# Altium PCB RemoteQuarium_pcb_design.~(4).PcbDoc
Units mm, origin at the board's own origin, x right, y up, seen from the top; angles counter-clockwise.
Board outline 63.5 x 89.41 mm, 2 copper layers (F.Cu, B.Cu); 22 components, 37 nets, 118 pads, 0 vias.
Unrouted connection lines stored in the file: 5.
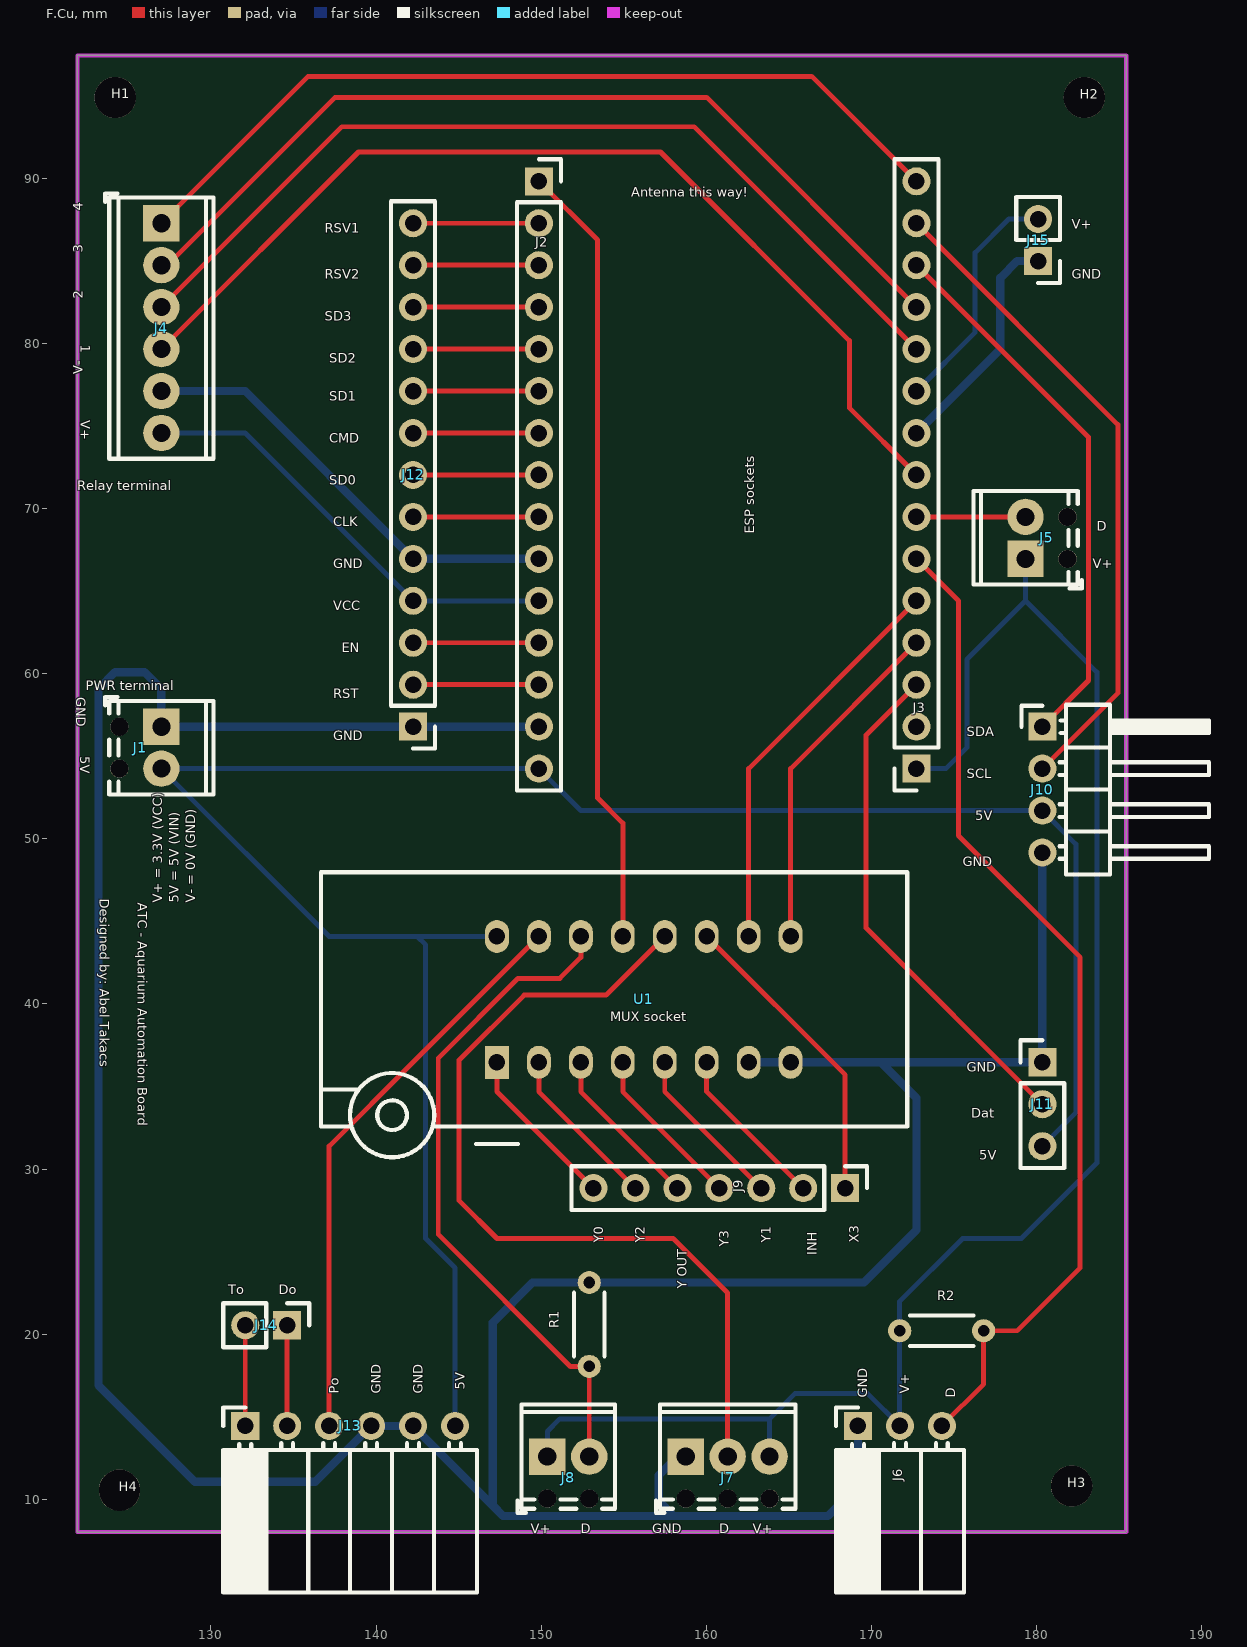
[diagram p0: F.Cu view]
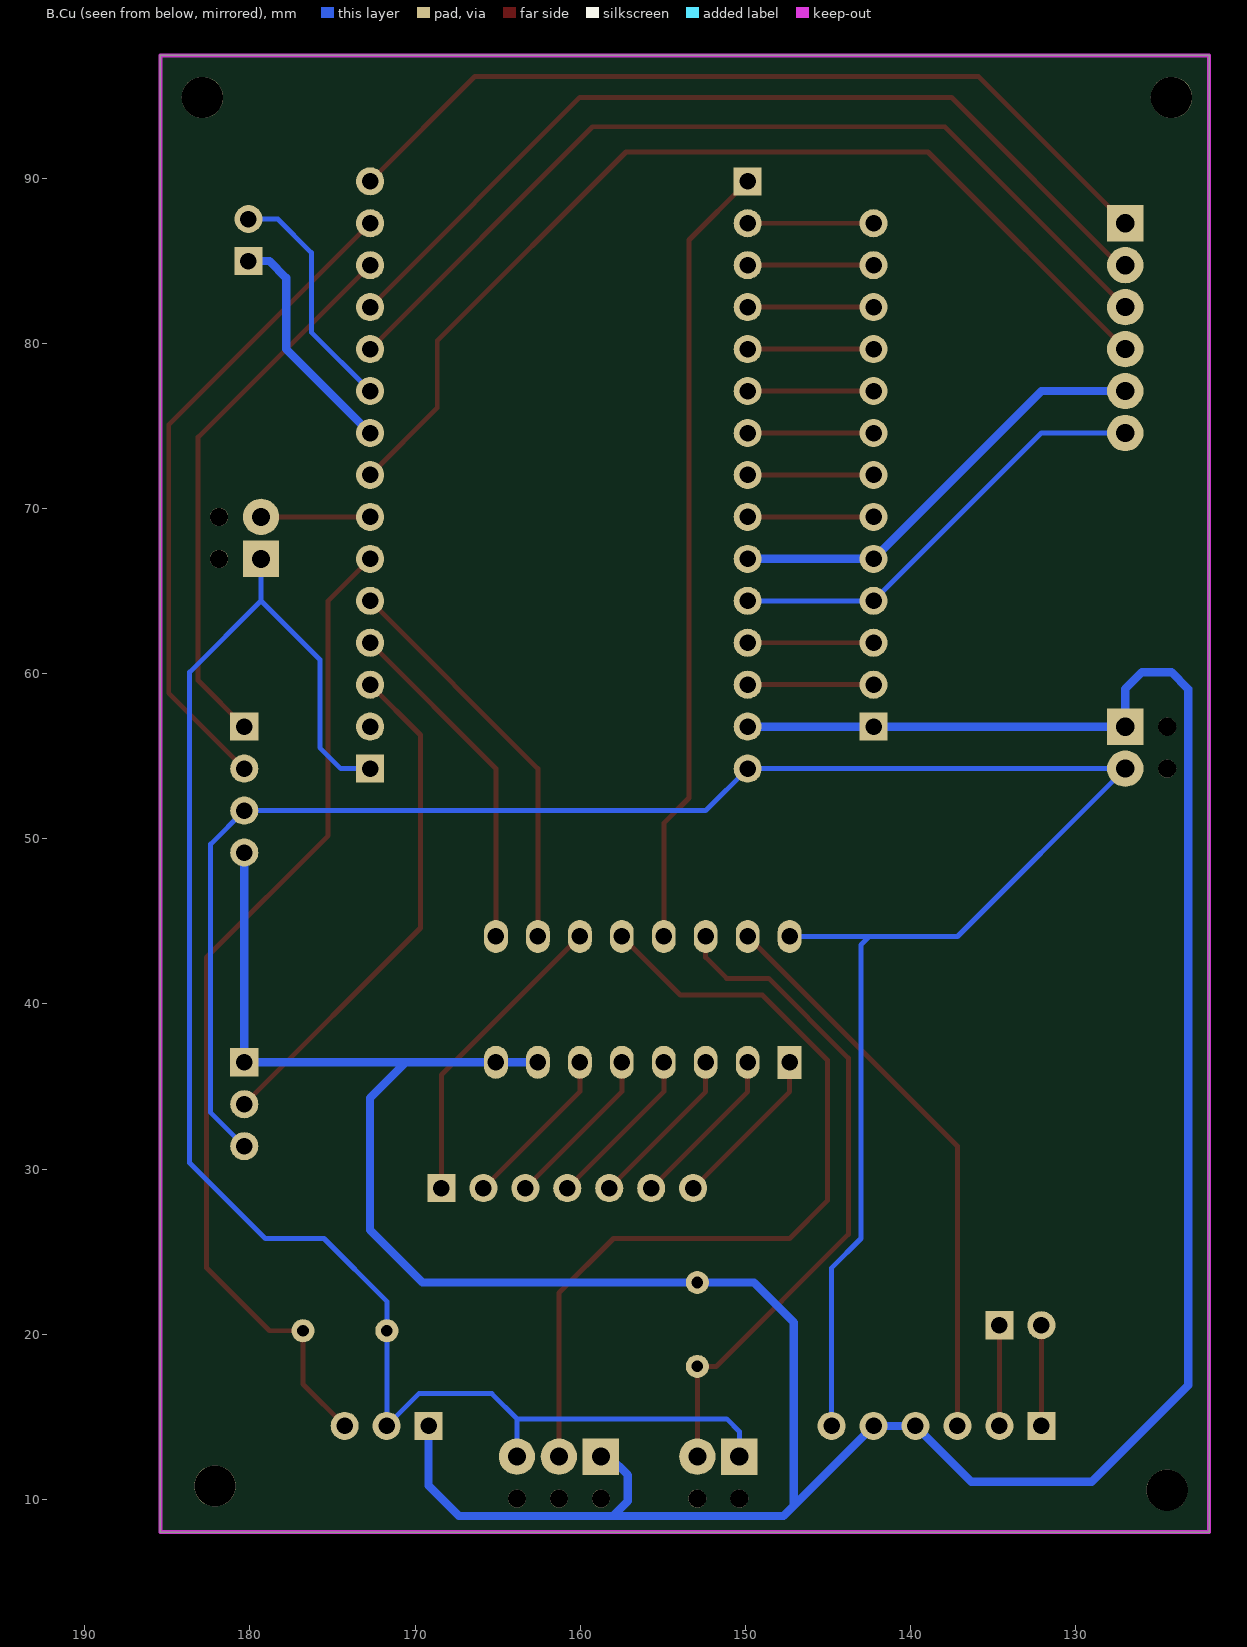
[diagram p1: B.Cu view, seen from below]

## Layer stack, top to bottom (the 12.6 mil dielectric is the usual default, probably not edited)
F.Mask: solder mask 0.0102, Solder Resist, Dk 3.5
F.Cu: signal copper 0.0356
Dielectric 1: dielectric 0.32, FR-4, Dk 4.8
B.Cu: signal copper 0.0356
B.Mask: solder mask 0.0102, Solder Resist, Dk 3.5

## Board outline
185.42,8.018 185.42,97.426 121.92,97.426 121.92,8.018 185.42,8.018

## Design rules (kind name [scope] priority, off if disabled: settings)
MinimumSolderMaskSliver [All] p1: minsoldermaskwidth=0
PolygonConnect [All] p1: connectstyle=Direct reliefconductorwidth=0.254 reliefentries=4 polygonreliefangle="90 Angle" airgapwidth=0.254
RoutingVias [All] p1: holewidth=0.711 width=1.27 viastyle="Through Hole" minholewidth=0.711 minwidth=1.27 maxholewidth=0.711 maxwidth=1.27
SilkToSilkClearance [All] p1: silktosilkclearance=0
SilkToSolderMaskClearance [IsPad] p1: minsilkscreentomaskgap=0 clearancetoexposedcopper=TRUE
SolderMaskExpansion [All] p1: expansion=0.102 istentingtop=FALSE
Width [All] p1: maxlimit=10 minlimit=0.254 preferedwidth=0.254 minimp=50.000000 maximp=50.000000 favimp=50.000000
26 further rules are at their usual default settings.

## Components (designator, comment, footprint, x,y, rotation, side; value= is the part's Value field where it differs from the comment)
H1 "MountingHole" MountingHole_2.5mm 124.206,94.886 r0 top
H2 "MountingHole" MountingHole_2.5mm 182.88,94.886 r0 top
H3 "MountingHole" MountingHole_2.5mm 182.118,10.812 r0 top
H4 "MountingHole" MountingHole_2.5mm 124.46,10.558 r0 top
J1 "Power_terminal" TerminalBlock_Phoenix_MPT-0,5-2-2.54_1x02_P2.54mm_Horizontal 127,56.786 r270 top
J2 "ESP left side sockets" PinSocket_1x15_P2.54mm_Vertical 149.86,89.806 r0 top
J3 "ESP right side sockets" PinSocket_1x15_P2.54mm_Vertical 172.72,54.246 r180 top
J4 "Relay_terminal" TerminalBlock_Phoenix_MPT-0,5-6-2.54_1x06_P2.54mm_Horizontal 127,87.266 r270 top
J5 "Calibration_btn" TerminalBlock_Phoenix_MPT-0,5-2-2.54_1x02_P2.54mm_Horizontal 179.324,66.946 r90 top
J6 "Temp_sensor_socket" PinSocket_1x03_P2.54mm_Horizontal 169.179,14.45 r90 top
J7 "Water_sensor_terminal" TerminalBlock_Phoenix_MPT-0,5-3-2.54_1x03_P2.54mm_Horizontal 158.75,12.59 r0 top
J8 "Light_sensor_terminal" TerminalBlock_Phoenix_MPT-0,5-2-2.54_1x02_P2.54mm_Horizontal 150.368,12.59 r0 top
J9 "MUX_pins" PinHeader_1x07_P2.54mm_Vertical 168.402,28.846 r270 top
J10 "LCD_pins" PinHeader_1x04_P2.54mm_Horizontal 180.34,56.786 r0 top
J11 "Feeder_servo_pins" PinHeader_1x03_P2.54mm_Vertical 180.34,36.466 r0 top
J12 "ESP_pins" PinHeader_1x13_P2.54mm_Vertical 142.24,56.786 r180 top
J13 "PH_sensor_sockets" PinSocket_1x06_P2.54mm_Horizontal 132.08,14.45 r90 top
J14 "Ph_sesnor-pins" PinHeader_1x02_P2.54mm_Vertical 134.62,20.546 r270 top
J15 "Vcc-GND" PinHeader_1x02_P2.54mm_Vertical 180.086,84.98 r180 top
R1 "10000" R_Axial_DIN0204_L3.6mm_D1.6mm_P5.08mm_Horizontal 152.908,18.051 r90 top
R2 "4700R" R_Axial_DIN0204_L3.6mm_D1.6mm_P5.08mm_Horizontal 171.704,20.21 r0 top
U1 "CD4052BE" DIP_Socket-16_W4.3_W5.08_W7.62_W10.16_W10.9_3M_216-3340-00-0602J 147.32,36.466 r90 top

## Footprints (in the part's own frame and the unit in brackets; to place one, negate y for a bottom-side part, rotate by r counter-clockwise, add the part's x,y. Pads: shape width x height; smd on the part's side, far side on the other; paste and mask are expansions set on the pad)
DIP_Socket-16_W4.3_W5.08_W7.62_W10.16_W10.9_3M_216-3340-00-0602J [mm]
  rect 2x1.44 hole 1 paste-2 mask+0: 1(0,0)
  rrect100% 2x1.44 hole 1 paste-2 mask+0: 2(0,-2.54) 3(0,-5.08) 4(0,-7.62) 5(0,-10.16) 6(0,-12.7) 7(0,-15.24) 8(0,-17.78) 9(7.62,-17.78) 10(7.62,-15.24) 11(7.62,-12.7) 12(7.62,-10.16) 13(7.62,-7.62) 14(7.62,-5.08) 15(7.62,-2.54) 16(7.62,0)
  silkscreen extent -5.75,-24.84 11.51,10.66
MountingHole_2.5mm [mm]
  round 2.5 hole 2.5 paste-2.5 mask+0: Un1(0,0)
PinHeader_1x02_P2.54mm_Vertical [mm]
  rect 1.7x1.7 hole 1 paste-1.7 mask+0: 1(0,0)
  rrect100% 1.7x1.7 hole 1 paste-1.7 mask+0: 2(0,-2.54)
  silkscreen extent -1.33,-3.87 1.33,1.33
PinHeader_1x03_P2.54mm_Vertical [mm]
  rect 1.7x1.7 hole 1 paste-1.7 mask+0: 1(0,0)
  rrect100% 1.7x1.7 hole 1 paste-1.7 mask+0: 2(0,-2.54) 3(0,-5.08)
  silkscreen extent -1.33,-6.41 1.33,1.33
PinHeader_1x04_P2.54mm_Horizontal [mm]
  rect 1.7x1.7 hole 1 paste-1.7 mask+0: 1(0,0)
  rrect100% 1.7x1.7 hole 1 paste-1.7 mask+0: 2(0,-2.54) 3(0,-5.08) 4(0,-7.62)
  silkscreen extent -1.27,-8.95 10.1,1.33
PinHeader_1x07_P2.54mm_Vertical [mm]
  rect 1.7x1.7 hole 1 paste-1.7 mask+0: 1(0,0)
  rrect100% 1.7x1.7 hole 1 paste-1.7 mask+0: 2(0,-2.54) 3(0,-5.08) 4(0,-7.62) 5(0,-10.16) 6(0,-12.7) 7(0,-15.24)
  silkscreen extent -1.33,-16.57 1.33,1.33
PinHeader_1x13_P2.54mm_Vertical [mm]
  rect 1.7x1.7 hole 1 paste-1.7 mask+0: 1(0,0)
  rrect100% 1.7x1.7 hole 1 paste-1.7 mask+0: 2(0,-2.54) 3(0,-5.08) 4(0,-7.62) 5(0,-10.16) 6(0,-12.7) 7(0,-15.24) 8(0,-17.78) 9(0,-20.32) 10(0,-22.86) 11(0,-25.4) 12(0,-27.94) 13(0,-30.48)
  silkscreen extent -1.33,-31.81 1.33,1.33
PinSocket_1x03_P2.54mm_Horizontal [mm]
  rect 1.7x1.7 hole 1 paste-1.7 mask+0: 1(0,0)
  rrect100% 1.7x1.7 hole 1 paste-1.7 mask+0: 2(0,-2.54) 3(0,-5.08)
  silkscreen extent -10.09,-6.41 1.11,1.33
PinSocket_1x06_P2.54mm_Horizontal [mm]
  rect 1.7x1.7 hole 1 paste-1.7 mask+0: 1(0,0)
  rrect100% 1.7x1.7 hole 1 paste-1.7 mask+0: 2(0,-2.54) 3(0,-5.08) 4(0,-7.62) 5(0,-10.16) 6(0,-12.7)
  silkscreen extent -10.09,-14.03 1.11,1.33
PinSocket_1x15_P2.54mm_Vertical [mm]
  rect 1.7x1.7 hole 1 paste-1.7 mask+0: 1(0,0)
  rrect100% 1.7x1.7 hole 1 paste-1.7 mask+0: 2(0,-2.54) 3(0,-5.08) 4(0,-7.62) 5(0,-10.16) 6(0,-12.7) 7(0,-15.24) 8(0,-17.78) 9(0,-20.32) 10(0,-22.86) 11(0,-25.4) 12(0,-27.94) 13(0,-30.48) 14(0,-33.02) 15(0,-35.56)
  silkscreen extent -1.33,-36.89 1.33,1.33
R_Axial_DIN0204_L3.6mm_D1.6mm_P5.08mm_Horizontal [mm]
  round 1.4 hole 0.7 paste-1.4 mask+0: 1(0,0)
  rrect100% 1.4x1.4 hole 0.7 paste-1.4 mask+0: 2(5.08,0)
  silkscreen extent 0.62,-0.92 4.46,0.92
TerminalBlock_Phoenix_MPT-0,5-2-2.54_1x02_P2.54mm_Horizontal [mm]
  rect 2.2x2.2 hole 1.1 paste-2.2 mask+0: 1(0,0)
  round 2.2 hole 1.1 paste-2.2 mask+0: 2(2.54,0)
  round 1.1 hole 1.1 paste-1.1 mask+0: Un1(0,-2.54) Un2(2.54,-2.54)
  silkscreen extent -1.8,-3.4 4.1,3.16
TerminalBlock_Phoenix_MPT-0,5-3-2.54_1x03_P2.54mm_Horizontal [mm]
  rect 2.2x2.2 hole 1.1 paste-2.2 mask+0: 1(0,0)
  round 2.2 hole 1.1 paste-2.2 mask+0: 2(2.54,0) 3(5.08,0)
  round 1.1 hole 1.1 paste-1.1 mask+0: Un1(0,-2.54) Un2(2.54,-2.54) Un3(5.08,-2.54)
  silkscreen extent -1.8,-3.4 6.64,3.16
TerminalBlock_Phoenix_MPT-0,5-6-2.54_1x06_P2.54mm_Horizontal [mm]
  rect 2.2x2.2 hole 1.1 paste-2.2 mask+0: 1(0,0)
  round 2.2 hole 1.1 paste-2.2 mask+0: 2(2.54,0) 3(5.08,0) 4(7.62,0) 5(10.16,0) 6(12.7,0)
  silkscreen extent -1.8,-3.4 14.26,3.16

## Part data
H1 H2 H3 H4: library part MountingHole_2.5mm, "Mounting Hole 2.5mm, no annular"
J1 J5 J8: library part TerminalBlock_Phoenix_MPT-0,5-2-2.54_1x02_P2.54mm_Horizontal, "Terminal Block Phoenix MPT-0,5-2-2.54, 2 pins, pitch 2.54mm, size 5.54x6.2mm^2, drill diamater 1.1mm, pad diameter 2.2mm, see http://www.mouser.com/ds/2/324/ItemDetail_1725656-920552.pdf, script-generated using https://github.com/pointhi/kicad-footprint-generator/scripts/TerminalBlock_Phoenix"
J2 J3: library part PinSocket_1x15_P2.54mm_Vertical, "Through hole straight socket strip, 1x15, 2.54mm pitch, single row (from Kicad 4.0.7), script generated"
J4: library part TerminalBlock_Phoenix_MPT-0,5-6-2.54_1x06_P2.54mm_Horizontal, "Terminal Block Phoenix MPT-0,5-6-2.54, 6 pins, pitch 2.54mm, size 15.7x6.2mm^2, drill diamater 1.1mm, pad diameter 2.2mm, see http://www.mouser.com/ds/2/324/ItemDetail_1725672-916605.pdf, script-generated using https://github.com/pointhi/kicad-footprint-generator/scripts/TerminalBlock_Phoenix"
J6: library part PinSocket_1x03_P2.54mm_Horizontal, "Through hole angled socket strip, 1x03, 2.54mm pitch, 8.51mm socket length, single row (from Kicad 4.0.7), script generated"
J7: library part TerminalBlock_Phoenix_MPT-0,5-3-2.54_1x03_P2.54mm_Horizontal, "Terminal Block Phoenix MPT-0,5-3-2.54, 3 pins, pitch 2.54mm, size 8.08x6.2mm^2, drill diamater 1.1mm, pad diameter 2.2mm, see http://www.mouser.com/ds/2/324/ItemDetail_1725656-920552.pdf, script-generated using https://github.com/pointhi/kicad-footprint-generator/scripts/TerminalBlock_Phoenix"
J9: library part PinHeader_1x07_P2.54mm_Vertical, "Through hole straight pin header, 1x07, 2.54mm pitch, single row"
J10: library part PinHeader_1x04_P2.54mm_Horizontal, "Through hole angled pin header, 1x04, 2.54mm pitch, 6mm pin length, single row"
J11: library part PinHeader_1x03_P2.54mm_Vertical, "Through hole straight pin header, 1x03, 2.54mm pitch, single row"
J12: library part PinHeader_1x13_P2.54mm_Vertical, "Through hole straight pin header, 1x13, 2.54mm pitch, single row"
J13: library part PinSocket_1x06_P2.54mm_Horizontal, "Through hole angled socket strip, 1x06, 2.54mm pitch, 8.51mm socket length, single row (from Kicad 4.0.7), script generated"
J14 J15: library part PinHeader_1x02_P2.54mm_Vertical, "Through hole straight pin header, 1x02, 2.54mm pitch, single row"
R1 R2: library part R_Axial_DIN0204_L3.6mm_D1.6mm_P5.08mm_Horizontal, "Resistor, Axial_DIN0204 series, Axial, Horizontal, pin pitch=5.08mm, 0.167W, length*diameter=3.6*1.6mm^2, http://cdn-reichelt.de/documents/datenblatt/B400/1_4W%23YAG.pdf"
U1: library part DIP_Socket-16_W4.3_W5.08_W7.62_W10.16_W10.9_3M_216-3340-00-0602J, "3M 16-pin zero insertion force socket, through-hole, row spacing 7.62 mm (300 mils), http://multimedia.3m.com/mws/media/494546O/3mtm-dip-sockets-100-2-54-mm-ts0365.pdf", Package="PDIP-16 Texas Instruments"

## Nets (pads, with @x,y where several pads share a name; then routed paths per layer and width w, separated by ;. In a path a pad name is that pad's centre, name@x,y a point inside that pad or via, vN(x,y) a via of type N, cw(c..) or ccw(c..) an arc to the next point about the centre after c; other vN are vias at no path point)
A0: J2.1 U1.13 | length 47.8
  F.Cu w0.3: J2.1 153.416,86.25 153.416,52.468 154.94,50.944 154.94,48.912 U1.13
CLK: J2.9 J12.6 | length 7.6
  F.Cu w0.3: J12.6 J2.9
CMD: J2.7 J12.8 | length 7.6
  F.Cu w0.3: J12.8 J2.7
D0: J3.15 J4.1 | length 52
  F.Cu w0.3: J4.1 135.89,96.156 166.37,96.156 J3.15
D3: J3.12 J4.2 | length 55.2
  F.Cu w0.3: J4.2 127.36,84.726 137.52,94.886 160.02,94.886 J3.12
D4: J3.11 J4.3 | length 55.8
  F.Cu w0.3: J4.3 137.922,93.108 159.258,93.108 J3.11
D5: J3.8 J4.4 | length 61.1
  F.Cu w0.3: J4.4 138.938,91.584 157.226,91.584 168.656,80.154 168.656,76.09 J3.8
D6: J3.7 J5.2 | length 6.6
  F.Cu w0.3: J3.7 J5.2
D7: J3.6 J6.3 R2.2 | length 61.3
  F.Cu w0.3: J3.6 175.26,64.406 175.26,50.182 182.626,42.816 182.626,24.02 178.816,20.21 R2.2 176.784,16.975 J6.3
D8: J3.5 U1.10 | length 24.5
  F.Cu w0.3: U1.10 162.56,49.166 162.56,54.246 J3.5
Do: J13.2 J14.1 | length 6.1
  F.Cu w0.3: J13.2 J14.1
EN: J2.12 J12.3 | length 7.6
  F.Cu w0.3: J12.3 J2.12
GND: J1.1 J2.10 J2.14 J3.2 J3.9 J4.5 J6.1 J7.1 J10.4 J11.1 J12.1 J12.5 J13.4 J13.5 J15.1 R1.2 U1.7 U1.8 | length 256.1
  B.Cu w0.5: J4.5 132.08,77.106 J12.5 J2.10 ; J2.14 J12.1 J1.1 127,59.072 125.984,60.088 124.206,60.088 123.19,59.072 123.19,16.908 129.032,11.066 136.316,11.066 J13.4 J13.5 147.69,9 ; J7.1 158.242,12.59 157.119,11.467 157.119,9.903 158.022,9 ; U1.7 U1.8 170.561,36.466 170.624,36.403 ; J6.1 169.179,10.827 167.352,9 158.022,9 ; J3.9 177.8,79.646 177.8,83.964 178.816,84.98 J15.1 ; J10.4 J11.1 170.688,36.466 170.624,36.403 ; 147.69,9 158.022,9 ; 147.69,9 147.066,9.624 147.066,20.718 149.479,23.131 R1.2 169.545,23.131 172.72,26.306 172.72,34.307 170.624,36.403
INH: J9.2 U1.6 | length 10
  F.Cu w0.3: U1.6 160.02,34.688 J9.2
LIGHT_DAT: J8.2 R1.1 U1.14 | length 40.9
  F.Cu w0.3: U1.14 152.4,42.816 151.13,41.546 148.59,41.546 143.764,36.72 143.764,26.052 151.765,18.051 R1.1 J8.2@152.908,12.717
P0: J13.3 U1.15 | length 34.9
  F.Cu w0.3: J13.3 137.16,31.386 142.24,36.466 U1.15
RST: J2.13 J12.2 | length 7.6
  F.Cu w0.3: J12.2 J2.13
RSV1: J2.2 J12.13 | length 7.6
  F.Cu w0.3: J12.13 J2.2
RSV2: J2.3 J12.12 | length 7.6
  F.Cu w0.3: J12.12 J2.3
RX: J3.4 U1.9 | length 20.9
  F.Cu w0.3: U1.9 165.1,49.166 165.1,54.246 J3.4
SCL: J3.14 J10.2 | length 40
  F.Cu w0.3: J3.14 184.912,75.074 184.912,58.818 J10.2
SD0: J2.8 J12.7 | length 7.6
  F.Cu w0.3: J12.7 J2.8
SD1: J2.6 J12.9 | length 7.6
  F.Cu w0.3: J12.9 J2.6
SD2: J2.5 J12.10 | length 7.6
  F.Cu w0.3: J12.10 J2.5
SD3: J2.4 J12.11 | length 7.6
  F.Cu w0.3: J12.11 J2.4
SDA: J3.13 J10.1 | length 33.4
  F.Cu w0.3: J3.13 183.134,74.312 183.134,59.58 J10.1
T0: J13.1 J14.2 | length 6.1
  F.Cu w0.3: J13.1 J14.2
TX: J3.3 J11.2 | length 31.1
  F.Cu w0.3: J3.3 169.672,56.278 169.672,44.594 J11.2
VCC: J2.11 J3.1 J3.10 J4.6 J5.1 J6.2 J7.3 J8.1 J12.4 J15.2 R2.1 | length 144.3
  F.Cu w0.3: R2.1 R2.1@171.719,20.195
  B.Cu w0.3: J4.6 132.08,74.566 J12.4 J2.11 ; J8.1 150.368,14.114 151.13,14.876 163.83,14.876 ; J7.3 163.83,14.876 ; J6.2@171.719,13.875 J6.2 ; J3.1 174.498,54.246 175.768,55.516 175.768,60.85 179.324,64.406 ; J3.10 176.276,80.662 176.276,85.488 178.308,87.52 J15.2 ; J5.1 179.324,64.406 ; 163.83,14.876 165.354,16.4 169.769,16.4 J6.2 ; J6.2 171.704,14.465 R2.1 171.704,21.988 175.514,25.798 179.07,25.798 183.642,30.37 183.642,60.088 179.324,64.406
VIN: J1.2 J2.15 J10.3 J11.3 J13.6 U1.16 | length 132
  B.Cu w0.3: J13.6 144.78,24.02 143.002,25.798 143.002,43.578 142.494,44.086 142.24,44.086 ; U1.16 142.24,44.086 ; 160.02,51.706 160.274,51.706 ; J11.3 182.372,33.418 182.372,49.674 J10.3 160.274,51.706 ; 142.24,44.086 137.16,44.086 J1.2 J2.15 152.4,51.706 160.274,51.706
WATER_DAT: J7.2 U1.12 | length 52.5
  F.Cu w0.3: U1.12 153.924,40.53 148.964,40.53 145.034,36.6 145.034,28.084 147.32,25.798 157.988,25.798 161.29,22.496 J7.2
X3: J9.1 U1.11 | length 18.7
  F.Cu w0.3: U1.11 168.402,35.704 J9.1
Y: J9.5 U1.3 | length 10
  F.Cu w0.3: U1.3 152.4,34.688 J9.5
Y0: J9.7 U1.1 | length 10
  F.Cu w0.3: U1.1 147.32,34.688 J9.7
Y1: J9.3 U1.5 | length 10
  F.Cu w0.3: U1.5 157.48,34.688 J9.3
Y2: J9.6 U1.2 | length 10.3
  F.Cu w0.3: U1.2 149.86,34.688 J9.6 J9.6@155.956,28.846
Y3: J9.4 U1.4 | length 10
  F.Cu w0.3: U1.4 154.94,34.688 J9.4
pads on no net: H1.Un1 H2.Un1 H3.Un1 H4.Un1 J1.Un1 J1.Un2 J5.Un1 J5.Un2 J7.Un1 J7.Un2 J7.Un3 J8.Un1 J8.Un2

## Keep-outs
Edge.Cuts:
  lines w0: 121.92,8.018 185.42,8.018 185.42,97.426 121.92,97.426 121.92,8.018
  lines w0.254: 121.92,8.018 185.42,8.018 185.42,97.426 121.92,97.426 121.92,8.018

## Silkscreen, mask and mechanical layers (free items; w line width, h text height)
F.SilkS:
  text "Antenna this way!" at 155.448,88.662 h1
  text "4" at 122.454,88.028 h1 r90
  text "V+" at 182.118,86.731 h1
  text "RSV1" at 136.906,86.474 h1
  text "3" at 122.459,85.488 h1 r90
  text "RSV2" at 136.906,83.68 h1
  text "GND" at 182.118,83.68 h1
  text "2" at 122.454,82.694 h1 r90
  text "SD3" at 136.906,81.138 h1
  text "1" at 121.897,79.9 h1 r270
  text "SD2" at 137.16,78.6 h1
  text "V-" at 122.455,78.122 h1 r90
  text "SD1" at 137.16,76.314 h1
  text "V+" at 121.893,75.328 h1 r270
  text "CMD" at 137.16,73.774 h1
  text "SD0" at 137.16,71.232 h1
  text "Relay terminal" at 121.92,70.882 h1
  text "CLK" at 137.414,68.694 h1
  text "ESP sockets" at 163.1,68.47 h1 r90
  text "D" at 183.642,68.447 h1
  text "V+" at 183.388,66.157 h1
  text "GND" at 137.414,66.154 h1
  text "VCC" at 137.414,63.614 h1
  text "EN" at 137.922,61.081 h1
  text "PWR terminal" at 122.428,58.786 h1
  text "GND" at 121.636,58.564 h1 r270
  text "RST" at 137.414,58.28 h1
  text "SDA" at 175.768,55.994 h1
  text "GND" at 137.414,55.74 h1
  text "5V" at 121.892,55.008 h1 r270
  text "SCL" at 175.768,53.454 h1
  text "5V" at 176.276,50.916 h1
  text "GND" at 175.514,48.12 h1
  text "Designed by: Abel Takacs" at 123.062,46.372 h1 r270
  text "ATC - Aquarium Automation Board" at 125.35,46.118 h1 r270
  text "V+ = 3.3V (VCC) / 5V = 5V (VIN) / V- = 0V (GND)" at 129.272,46.118 h1 r90
  text "MUX socket" at 154.178,38.724 h1
  text "GND" at 175.768,35.674 h1
  text "Dat" at 176.022,32.882 h1
  text "5V" at 176.53,30.342 h1
  text "Y0" at 153.955,25.544 h1 r90
  text "Y2" at 156.49,25.544 h1 r90
  text "Y1" at 164.107,25.544 h1 r90
  text "X3" at 169.449,25.544 h1 r90
  text "Y3" at 161.575,25.29 h1 r90
  text "INH" at 166.901,24.782 h1 r90
  text "Y OUT" at 159.034,22.75 h1 r90
  text "To" at 131.064,22.214 h1
  text "Do" at 134.112,22.214 h1
  text "5V" at 145.57,16.654 h1 r90
  text "Po" at 137.95,16.4 h1 r90
  text "GND" at 140.492,16.4 h1 r90
  text "GND" at 143.032,16.4 h1 r90
  text "V+" at 172.493,16.4 h1 r90
  text "GND" at 169.956,16.146 h1 r90
  text "D" at 175.283,16.146 h1 r90
  text "V+" at 149.352,7.737 h1
  text "D" at 152.4,7.741 h1
  text "D" at 160.782,7.741 h1
  text "V+" at 162.814,7.737 h1
  text "GND" at 156.718,7.734 h1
